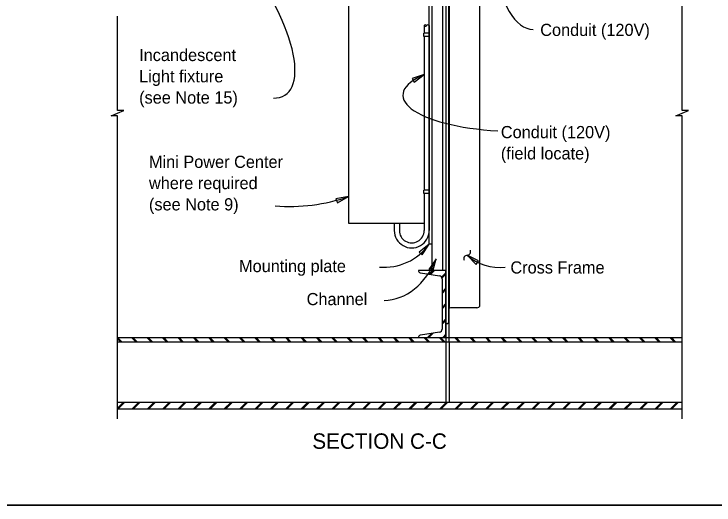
# Model space of a CAD drawing. Extents: x 0 to 30.8, y 0 to 21.2.
# Drawn here: x 12.47 to 21.15, y 0 to 6.1 of the extents above; entities that cross this region are included whole.
import ezdxf

# ---------------------------------------------------------------- set-up
doc = ezdxf.new("R2010")
doc.units = 0
for name, color, linetype in [('ActivePts-ConstElements', 7, 'Continuous'), ('Dimension', 7, 'Continuous'), ('Lighting', 7, 'Continuous'), ('Miscellaneous', 7, 'Continuous'), ('Miscellaneous1', 7, 'Continuous'), ('SteelGirder', 7, 'Continuous'), ('SteelGirder_h', 7, 'Continuous'), ('TextStructures', 7, 'Continuous')]:
    doc.layers.add(name, color=color, linetype=linetype)

msp = doc.modelspace()

# ---------------------------------------------------------------- linework, layer by layer
at = {"layer": 'ActivePts-ConstElements'}
msp.add_lwpolyline([(0, 0), (30.7879, 0), (30.7879, 19.4596), (0, 19.4596)], close=True, dxfattribs=at)
at = {"layer": 'Dimension'}
for points in [[(20.7608, 1.0713), (20.7608, 4.831), (20.6833, 4.831), (20.7608, 4.8647), (20.8383, 4.8985), (20.7608, 4.8985), (20.7608, 6.9989)], [(13.7516, 1.0713), (13.7516, 4.831), (13.6741, 4.831), (13.7516, 4.8647), (13.8291, 4.8985), (13.7516, 4.8985), (13.7516, 6.069)]]:
    msp.add_lwpolyline(points, dxfattribs=at)
for points in [[(17.5576, 5.3459), (17.4075, 5.2954), (17.4325, 5.2487)], [(16.6201, 3.829), (16.4638, 3.8033), (16.481, 3.7532)], [(17.6201, 3.2371), (17.4948, 3.1401), (17.5338, 3.1043)], [(17.7077, 3.0557), (17.617, 2.9258), (17.6649, 2.9032)], [(18.0926, 3.1011), (18.2026, 2.9871), (18.234, 3.0297)]]:
    msp.add_lwpolyline(points, close=True, dxfattribs=at)
for centre, radius, start, end in [((15.8901, 5.9525), 2.2455, 265.3641, 288.97308), ((17.0608, 3.6412), 0.6901, 265.09847, 324.1488), ((18.0905, 3.1454), 0.0447, 272.35831, 24.08553), ((18.0941, 3.0561), 0.0447, 92.35831, 204.08553), ((18.4906, 3.546), 0.5969, 228.179, 277.09313)]:
    msp.add_arc(centre, radius, start, end, dxfattribs=at)
for centre, major_axis, ratio, start_param, end_param in [((14.9763, 6.3138), (-0.8636, 1.2185), 0.378675, 2.874358, 4.819841), ((18.903, 7.0853), (0.0076, -1.1813), 0.426092, 5.02876, 6.283138), ((18.7641, 5.0873), (1.4705, 0), 0.307602, 2.532927, 4.511363), ((17.0461, 3.5289), (-0.0147, 0.9882), 0.759061, 3.141594, 4.201813)]:
    msp.add_ellipse(centre, major_axis=major_axis, ratio=ratio, start_param=start_param, end_param=end_param, dxfattribs=at)
at = {"layer": 'Lighting'}
for p, q in [((17.7867, 7.3502), (17.7867, 2.9127)), ((17.5576, 5.9527), (17.5576, 5.8576)), ((17.6201, 5.9527), (17.6201, 3.4079)), ((17.5576, 5.8159), (17.5576, 3.9083)), ((17.5576, 3.8666), (17.5576, 3.4079)), ((17.1876, 3.4996), (17.1876, 3.4079)), ((17.2501, 3.4996), (17.2501, 3.4079)), ((17.6513, 3.2371), (17.6513, 2.9127))]:
    msp.add_line(p, q, dxfattribs=at)
msp.add_lwpolyline([(17.6201, 3.4996), (17.6201, 6.2246), (16.6201, 6.2246), (16.6201, 3.4996), (17.5576, 3.4996)], dxfattribs=at)
for centre, radius, start, end in [((17.5733, 5.944), 0.0179, 29.00268, 150.99744), ((17.5733, 5.9614), 0.0179, 209.00301, 330.9971), ((17.6046, 5.944), 0.0179, 29.00279, 150.99732), ((17.4039, 3.4079), 0.2162, 180, 0.00803), ((17.4039, 3.4079), 0.1537, 180, 0.00803)]:
    msp.add_arc(centre, radius, start, end, dxfattribs=at)
at = {"layer": 'Miscellaneous'}
for p, q in [((17.4884, 2.907), (17.4941, 2.9127)), ((17.6211, 2.8664), (17.6674, 2.9127)), ((17.6363, 2.8639), (17.685, 2.9127)), ((17.7736, 2.828), (17.8284, 2.8828)), ((17.7791, 2.8158), (17.8284, 2.8651)), ((17.7805, 2.644), (17.8284, 2.6919)), ((17.7805, 2.6263), (17.8284, 2.6742)), ((17.7805, 2.453), (17.8284, 2.5009)), ((17.7805, 2.4354), (17.8284, 2.4833)), ((17.7805, 2.2621), (17.8284, 2.31)), ((17.7805, 2.2444), (17.8284, 2.2924)), ((17.5977, 2.0793), (17.6484, 2.1301)), ((17.6154, 2.0793), (17.6695, 2.1335)), ((17.7886, 2.0793), (17.8284, 2.1191)), ((17.8063, 2.0793), (17.8284, 2.1014)), ((13.7877, 2.0272), (13.7516, 2.0633)), ((13.8053, 2.0272), (13.7532, 2.0794)), ((13.9786, 2.0272), (13.9265, 2.0794)), ((13.9963, 2.0272), (13.9441, 2.0794)), ((14.1695, 2.0272), (14.1174, 2.0794)), ((14.1872, 2.0272), (14.135, 2.0794)), ((14.3604, 2.0272), (14.3083, 2.0794)), ((14.3781, 2.0272), (14.326, 2.0794)), ((14.5513, 2.0272), (14.4992, 2.0794)), ((14.569, 2.0272), (14.5169, 2.0794)), ((14.7423, 2.0272), (14.6901, 2.0794)), ((14.7599, 2.0272), (14.7078, 2.0794)), ((14.9332, 2.0272), (14.881, 2.0794)), ((14.9509, 2.0272), (14.8987, 2.0794)), ((15.1241, 2.0272), (15.072, 2.0794)), ((15.1418, 2.0272), (15.0896, 2.0794)), ((15.315, 2.0272), (15.2629, 2.0794)), ((15.3327, 2.0272), (15.2806, 2.0794)), ((15.5059, 2.0272), (15.4538, 2.0794)), ((15.5236, 2.0272), (15.4715, 2.0794)), ((15.6969, 2.0272), (15.6447, 2.0794)), ((15.7145, 2.0272), (15.6624, 2.0794)), ((15.8878, 2.0272), (15.8356, 2.0794)), ((15.9054, 2.0272), (15.8533, 2.0794)), ((16.0787, 2.0272), (16.0266, 2.0794)), ((16.0964, 2.0272), (16.0442, 2.0794)), ((16.2696, 2.0272), (16.2175, 2.0794)), ((16.2873, 2.0272), (16.2352, 2.0794)), ((16.4605, 2.0272), (16.4084, 2.0794)), ((16.4782, 2.0272), (16.4261, 2.0794)), ((16.6514, 2.0272), (16.5993, 2.0794)), ((16.6691, 2.0272), (16.617, 2.0794)), ((16.8424, 2.0272), (16.7902, 2.0794)), ((16.86, 2.0272), (16.8079, 2.0794)), ((17.0333, 2.0272), (16.9812, 2.0794)), ((17.051, 2.0272), (16.9988, 2.0794)), ((17.2242, 2.0272), (17.1721, 2.0794)), ((17.2419, 2.0272), (17.1897, 2.0794)), ((17.4151, 2.0272), (17.363, 2.0794)), ((17.4328, 2.0272), (17.3807, 2.0794)), ((17.606, 2.0272), (17.5539, 2.0794)), ((17.6237, 2.0272), (17.5716, 2.0794)), ((17.797, 2.0272), (17.7448, 2.0794)), ((17.8146, 2.0272), (17.7625, 2.0794)), ((17.9879, 2.0272), (17.9357, 2.0794)), ((18.0056, 2.0272), (17.9534, 2.0794)), ((18.1788, 2.0272), (18.1267, 2.0794)), ((18.1965, 2.0272), (18.1443, 2.0794)), ((18.3697, 2.0272), (18.3176, 2.0794)), ((18.3874, 2.0272), (18.3353, 2.0794)), ((18.5606, 2.0272), (18.5085, 2.0794)), ((18.5783, 2.0272), (18.5262, 2.0794)), ((18.7516, 2.0272), (18.6994, 2.0794)), ((18.7692, 2.0272), (18.7171, 2.0794)), ((18.9425, 2.0272), (18.8903, 2.0794)), ((18.9602, 2.0272), (18.908, 2.0794)), ((19.1334, 2.0272), (19.0813, 2.0794)), ((19.1511, 2.0272), (19.0989, 2.0794)), ((19.3243, 2.0272), (19.2722, 2.0794)), ((19.342, 2.0272), (19.2899, 2.0794)), ((19.5152, 2.0272), (19.4631, 2.0794)), ((19.5329, 2.0272), (19.4808, 2.0794)), ((19.7062, 2.0273), (19.654, 2.0794)), ((19.7238, 2.0273), (19.6717, 2.0794)), ((19.8971, 2.0273), (19.8449, 2.0794)), ((19.9148, 2.0273), (19.8626, 2.0794)), ((20.088, 2.0273), (20.0359, 2.0794)), ((20.1057, 2.0273), (20.0535, 2.0794)), ((20.2789, 2.0273), (20.2268, 2.0794)), ((20.2966, 2.0273), (20.2445, 2.0794)), ((20.4698, 2.0273), (20.4177, 2.0794)), ((20.4875, 2.0273), (20.4354, 2.0794)), ((20.6608, 2.0273), (20.6086, 2.0794)), ((20.6784, 2.0273), (20.6263, 2.0794)), ((13.7516, 1.204), (13.825, 1.2774)), ((13.7594, 1.1941), (13.8426, 1.2774)), ((13.9326, 1.1941), (14.0159, 1.2774)), ((13.9503, 1.1941), (14.0336, 1.2774)), ((14.1235, 1.1941), (14.2068, 1.2774)), ((14.1412, 1.1941), (14.2245, 1.2774)), ((14.3144, 1.1941), (14.3977, 1.2774)), ((14.3321, 1.1941), (14.4154, 1.2774)), ((14.5054, 1.1941), (14.5886, 1.2774)), ((14.523, 1.1941), (14.6063, 1.2774)), ((14.6963, 1.1941), (14.7796, 1.2774)), ((14.714, 1.1941), (14.7972, 1.2774)), ((14.8872, 1.1941), (14.9705, 1.2774)), ((14.9049, 1.1941), (14.9882, 1.2774)), ((15.0781, 1.1941), (15.1614, 1.2774)), ((15.0958, 1.1941), (15.1791, 1.2774)), ((15.269, 1.1941), (15.3523, 1.2774)), ((15.2867, 1.1941), (15.37, 1.2774)), ((15.46, 1.1941), (15.5432, 1.2774)), ((15.4776, 1.1941), (15.5609, 1.2774)), ((15.6509, 1.1941), (15.7342, 1.2774)), ((15.6686, 1.1941), (15.7518, 1.2774)), ((15.8418, 1.1941), (15.9251, 1.2774)), ((15.8595, 1.1941), (15.9428, 1.2774)), ((16.0327, 1.1941), (16.116, 1.2774)), ((16.0504, 1.1941), (16.1337, 1.2774)), ((16.2236, 1.1941), (16.3069, 1.2774)), ((16.2413, 1.1941), (16.3246, 1.2774)), ((16.4146, 1.1941), (16.4978, 1.2774)), ((16.4322, 1.1941), (16.5155, 1.2774)), ((16.6055, 1.1941), (16.6888, 1.2774)), ((16.6231, 1.1941), (16.7064, 1.2774)), ((16.7964, 1.1941), (16.8797, 1.2774)), ((16.8141, 1.1941), (16.8973, 1.2774)), ((16.9873, 1.1941), (17.0706, 1.2774)), ((17.005, 1.1941), (17.0883, 1.2774)), ((17.1782, 1.1941), (17.2615, 1.2774)), ((17.1959, 1.1941), (17.2792, 1.2774)), ((17.3691, 1.1941), (17.4524, 1.2774)), ((17.3868, 1.1941), (17.4701, 1.2774)), ((17.5601, 1.1941), (17.6433, 1.2774)), ((17.5777, 1.1941), (17.661, 1.2774)), ((17.751, 1.1941), (17.8343, 1.2774)), ((17.7687, 1.1941), (17.8519, 1.2774)), ((17.9419, 1.1941), (18.0252, 1.2774)), ((17.9596, 1.1941), (18.0429, 1.2774)), ((18.1328, 1.1941), (18.2161, 1.2774)), ((18.1505, 1.1941), (18.2338, 1.2774)), ((18.3237, 1.1941), (18.407, 1.2774)), ((18.3414, 1.1941), (18.4247, 1.2774)), ((18.5147, 1.1941), (18.5979, 1.2774)), ((18.5323, 1.1941), (18.6156, 1.2774)), ((18.7056, 1.1941), (18.7889, 1.2774)), ((18.7233, 1.1941), (18.8065, 1.2774)), ((18.8965, 1.1941), (18.9798, 1.2774)), ((18.9142, 1.1941), (18.9975, 1.2774)), ((19.0874, 1.1941), (19.1707, 1.2774)), ((19.1051, 1.1941), (19.1884, 1.2774)), ((19.2783, 1.1941), (19.3616, 1.2774)), ((19.296, 1.1941), (19.3793, 1.2774)), ((19.4693, 1.1941), (19.5525, 1.2774)), ((19.4869, 1.1941), (19.5702, 1.2774)), ((19.6602, 1.1941), (19.7435, 1.2774)), ((19.6779, 1.1941), (19.7611, 1.2774)), ((19.8511, 1.1941), (19.9344, 1.2774)), ((19.8688, 1.1941), (19.9521, 1.2774)), ((20.042, 1.1941), (20.1253, 1.2774)), ((20.0597, 1.1941), (20.143, 1.2774)), ((20.2329, 1.1941), (20.3162, 1.2774)), ((20.2506, 1.1941), (20.3339, 1.2774)), ((20.4239, 1.1941), (20.5072, 1.2774)), ((20.4415, 1.1941), (20.5248, 1.2774)), ((20.6148, 1.1941), (20.6981, 1.2774)), ((20.6325, 1.1941), (20.7158, 1.2774))]:
    msp.add_line(p, q, dxfattribs=at)
at = {"layer": 'Miscellaneous1'}
msp.add_lwpolyline([(0, 19.8), (30.8, 19.8), (30.8, 0), (0, 0)], close=True, dxfattribs=at)
at = {"layer": 'SteelGirder'}
for p, q in [((18.2451, 7.3368), (18.2451, 2.4661)), ((17.8596, 7.1373), (17.8596, 2.2664)), ((17.8284, 6.9648), (17.8284, 2.0794)), ((17.6201, 5.8576), (17.5524, 5.8576)), ((17.5524, 5.8159), (17.5524, 5.8576)), ((17.6149, 5.8576), (17.6149, 5.8159)), ((17.6201, 5.8159), (17.5524, 5.8159)), ((17.6201, 3.9083), (17.5524, 3.9083)), ((17.5524, 3.8666), (17.5524, 3.9083)), ((17.6201, 3.8666), (17.5524, 3.8666)), ((17.6149, 3.9083), (17.6149, 3.8666)), ((17.8284, 2.9127), (17.4867, 2.9127)), ((17.5106, 2.8845), (17.7492, 2.8455)), ((17.8284, 2.0793), (17.8284, 2.9127)), ((17.7805, 2.8085), (17.7805, 2.1835)), ((17.8701, 2.0794), (17.8701, 2.4426)), ((18.2138, 2.4499), (17.9013, 2.4499)), ((17.7492, 2.1465), (17.5106, 2.1075)), ((13.7516, 2.0794), (20.7608, 2.0794)), ((13.7516, 2.0272), (20.7608, 2.0272)), ((17.4867, 2.0793), (17.8284, 2.0793)), ((17.8284, 2.0272), (17.8284, 1.2774)), ((17.8701, 2.0272), (17.8701, 1.2774)), ((13.7516, 1.2774), (20.7608, 1.2774)), ((13.7516, 1.1941), (20.7608, 1.1941))]:
    msp.add_line(p, q, dxfattribs=at)
msp.add_lwpolyline([(17.6201, 6.4871), (17.6513, 6.4871), (17.6513, 3.2371), (17.6201, 3.2371)], close=True, dxfattribs=at)
for centre, radius, start, end in [((17.5153, 2.9127), 0.0286, 180, 260.5), ((17.743, 2.8085), 0.0375, 360, 80.5), ((17.743, 2.1835), 0.0375, 279.5, 360), ((17.5153, 2.0793), 0.0286, 99.5, 180)]:
    msp.add_arc(centre, radius, start, end, dxfattribs=at)
for centre, major_axis, end_param in [((17.9013, 2.4284), (-0.0417, 0), 6.283185), ((18.2138, 2.4661), (0.0313, 0), 6.283185), ((17.8284, 2.2666), (0.0312, 0), 6.270045)]:
    msp.add_ellipse(centre, major_axis=major_axis, ratio=0.5176, start_param=4.712389, end_param=end_param, dxfattribs=at)
at = {"layer": 'SteelGirder_h'}
for p, q in [((17.8701, 7.3368), (17.8701, 2.4426)), ((17.8284, 2.0794), (17.8284, 2.0272)), ((17.8701, 2.0272), (17.8701, 2.0794))]:
    msp.add_line(p, q, dxfattribs=at)

# ---------------------------------------------------------------- texts
at = {"layer": 'Dimension'}
for s, p in [('Incandescent', (14.0211, 5.5118)), ('Light fixture', (14.0211, 5.2478)), ('(see Note 15)', (14.0211, 4.9838)), ('Conduit (120V)', (18.5098, 4.5545)), ('(field locate)', (18.5098, 4.2905)), ('Mini Power Center', (14.143, 4.1855)), ('where required', (14.143, 3.9215)), ('(see Note 9)', (14.143, 3.6575))]:
    msp.add_text(s, height=0.1512, dxfattribs=at).set_placement(p)
at = {"layer": 'TextStructures'}
for s, height, p in [('Conduit (120V)', 0.1512, (18.9986, 5.8235)), ('Mounting plate', 0.1512, (15.2608, 2.8913)), ('Cross Frame', 0.1512, (18.6286, 2.8741)), ('Channel', 0.1512, (16.0999, 2.4812)), ('SECTION C-C', 0.192, (16.1702, 0.6975))]:
    msp.add_text(s, height=height, dxfattribs=at).set_placement(p)

doc.saveas('drawing.dxf')
